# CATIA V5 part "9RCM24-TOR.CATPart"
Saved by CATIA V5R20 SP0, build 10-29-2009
Part number: 9RCM24-TOR
Revision: ANY
Definition: UNKNOWN
Nomenclature: 9RCM24-TOR
Source: Unknown
Bounding box of the stored display mesh (mm): x -9 to 9, y -9 to 9, z -19.4 to 5.1
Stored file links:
  C:\Users\Utente\Desktop\IO LAVORO\3D X SITO CF\CUMSA\3D files RCM\RCM 245712\9RCM24-TOR.CATPart
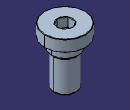
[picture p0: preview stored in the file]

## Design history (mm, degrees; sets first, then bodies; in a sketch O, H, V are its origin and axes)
Body1 "Cortar-Extruir3" (main body)
  Solid1: solid without history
